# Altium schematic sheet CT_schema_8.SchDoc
size 308 x 210 mm
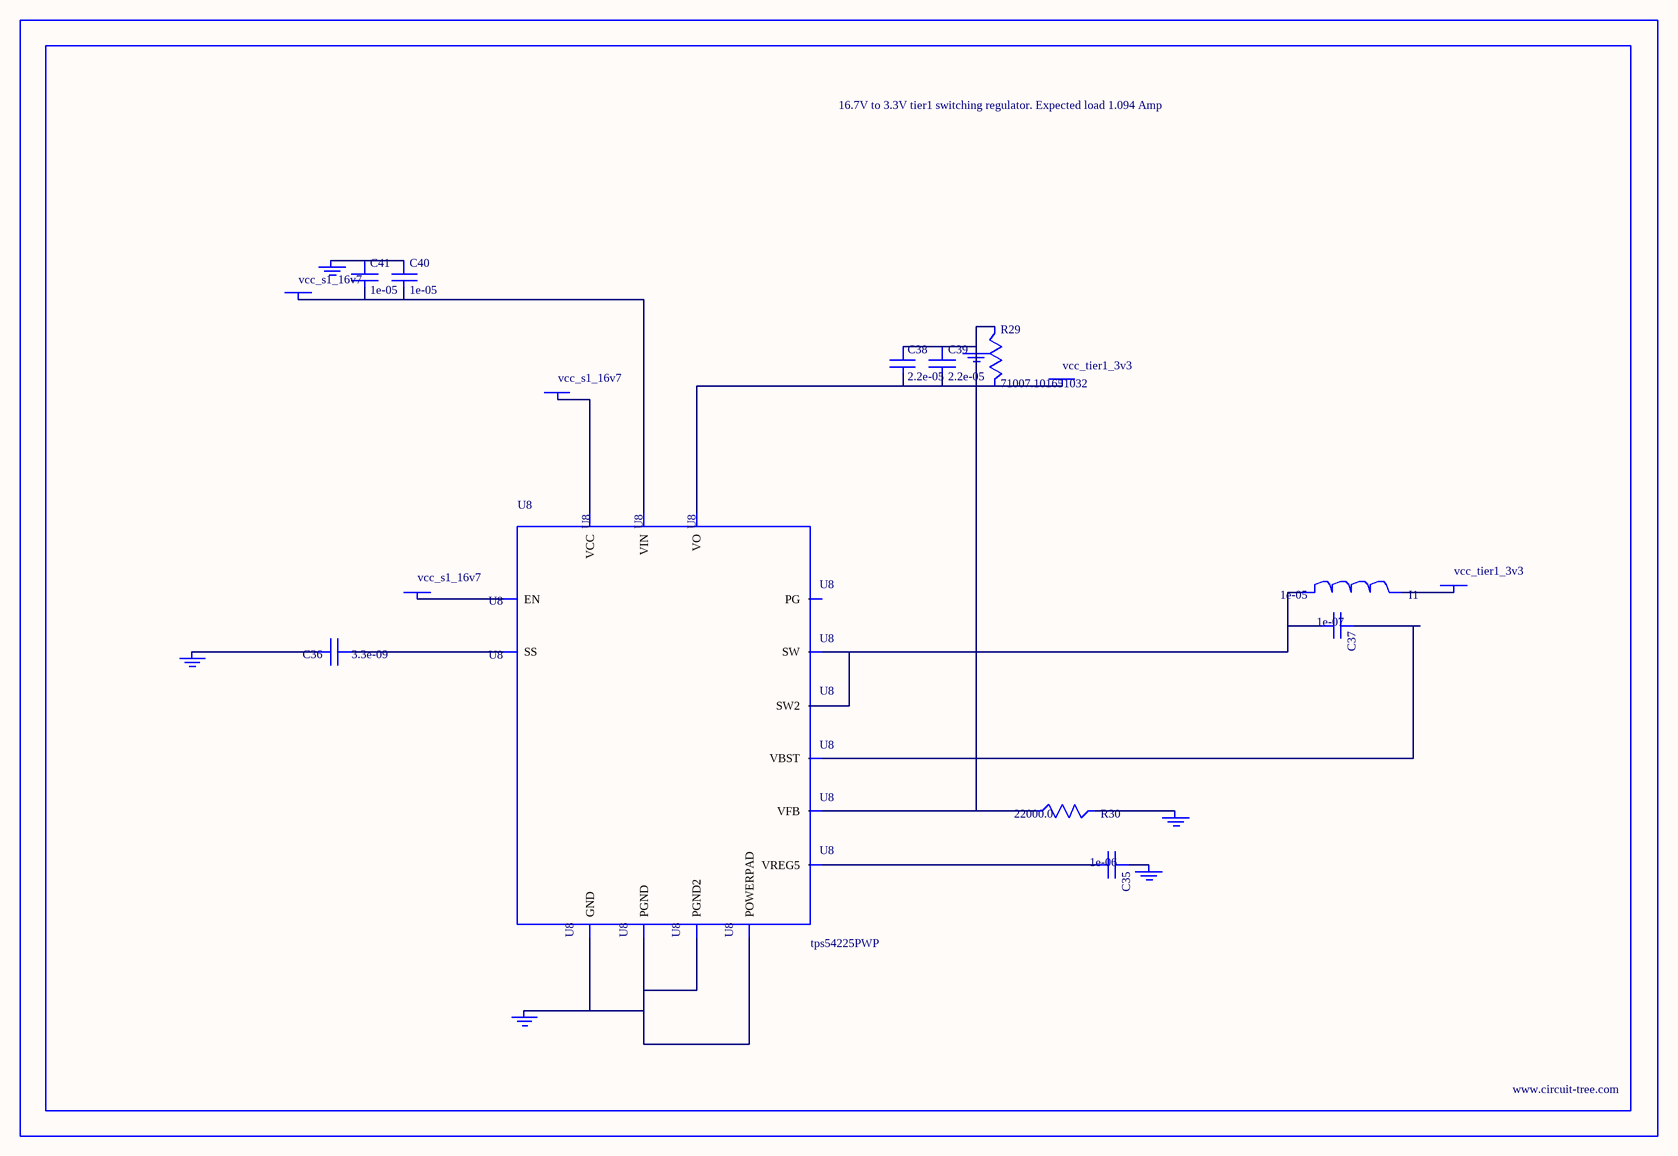
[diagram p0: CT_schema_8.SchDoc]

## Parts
BORDER7  (no value)
C35  1e-06  [C0603]
C36  3.3e-09  [C0402]
C37  1e-07  [C0402]
C38  2.2e-05  [C1210]
C39  2.2e-05  [C1210]
C40  1e-05  [C1210]
C41  1e-05  [C1210]
GND_INSTANCE_7_0  (no value)
GND_INSTANCE_7_1  (no value)
GND_INSTANCE_7_2  (no value)
GND_INSTANCE_7_3  (no value)
GND_INSTANCE_7_4  (no value)
GND_INSTANCE_7_5  (no value)
I1  1e-05  [IND_PM3316]
POWER_INSTANCE_7_0  vcc_tier1_3v3
POWER_INSTANCE_7_1  vcc_s1_16v7
POWER_INSTANCE_7_2  vcc_tier1_3v3
POWER_INSTANCE_7_3  vcc_s1_16v7
POWER_INSTANCE_7_4  vcc_s1_16v7
R29  71007.101651032  [R0603]
R30  22000.0  [R0603]
U8  tps54225PWP  [HTSSOP14]

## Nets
NetC35_1: C35.1 GND_INSTANCE_7_2.0(GND)
NetC35_2: C35.2 U8.3(VREG5)
NetC36_1: C36.1 U8.4(SS)
NetC36_2: C36.2 GND_INSTANCE_7_3.0(GND)
NetC37_1: C37.1 U8.12(VBST)
NetC37_2: C37.2 I1.1 U8.10(SW) U8.11(SW2)
NetC38_1: C38.1 C39.1 GND_INSTANCE_7_0.0(GND) R29.1 R30.1 U8.2(VFB)
NetC38_2: C38.2 C39.2 POWER_INSTANCE_7_0.0(PWR) R29.2 U8.1(VO)
NetC40_1: C40.1 C41.1 GND_INSTANCE_7_5.0(GND)
NetC40_2: C40.2 C41.2 POWER_INSTANCE_7_3.0(PWR) U8.13(VIN)
NetGND_INSTANCE_7_1_0: GND_INSTANCE_7_1.0(GND) R30.2
NetGND_INSTANCE_7_4_0: GND_INSTANCE_7_4.0(GND) U8.5(GND) U8.8(PGND) U8.9(PGND2) U8.15(POWERPAD)
NetI1_2: I1.2 POWER_INSTANCE_7_2.0(PWR)
NetPOWER_INSTANCE_7_1_0: POWER_INSTANCE_7_1.0(PWR) U8.7(EN)
NetPOWER_INSTANCE_7_4_0: POWER_INSTANCE_7_4.0(PWR) U8.14(VCC)

Not connected (* = marked no-connect by the designer): U8 6(PG)

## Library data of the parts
BORDER7 = BORDER_PAGE7
C35 = C0603C105K3RACTU
C36 = C0402C332K3RAC
C37 = C0402C104K3RACTU
C38 C39 = GRM32ER61E226ME15L
C40 C41 = C1210C106K5PACTU
GND_INSTANCE_7_0-GND_INSTANCE_7_5 = GND
I1 = PM3316-100M-RC
POWER_INSTANCE_7_0-POWER_INSTANCE_7_4 = PWR
R29 = R29
R30 = RC0603JR-0722KL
